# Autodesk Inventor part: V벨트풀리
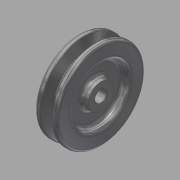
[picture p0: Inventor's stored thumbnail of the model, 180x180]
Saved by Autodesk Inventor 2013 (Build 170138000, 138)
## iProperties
Created: 2015-11
Part Number: V벨트풀리
Material: 강철, 탄소
Document SubType Name: Modeling
Designer: mduedu
Density: 7.87 g/cm^3
Mass: 415.435 g
Surface Area: 174.543 cm^2
Volume: 52.7872 cm^3
Author: mduedu
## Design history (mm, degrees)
sketch "스케치1"
  geometry: L1 (-9.5, 0)-(9.5, 0); L2 (0, 0)-(0, 37.7); L3 (-4.825, 37.7)-(-9.5, 37.7); L4 (-9.5, 37.7)-(-9.5, 0); L5 (0, 28.7)-(-2.074, 28.7); L6 (-2.074, 28.7)-(-4.825, 37.7); L7 (4.825, 37.7)-(9.5, 37.7); L8 (9.5, 37.7)-(9.5, 0); L9 (0, 28.7)-(2.074, 28.7); L10 (2.074, 28.7)-(4.825, 37.7); L11 (-9.5, 35)-(9.5, 35); 3 further points
  constraints: 22 end point, 7 point on line, 4 perpendicular, 3 symmetric about line, 1 coincident, 1 horizontal, 1 horizontal alignment, 1 midpoint, 1 vertical
  dimensions: "d0" = 19 distance of L1.start L1.end; "d2" = 75.4 diameter of L2.end L1 (derived); "d3" = 34 deg angle of L10 L6; "d4" = 6.3 distance between parallel lines of L11 L9; "d5" = 2.7 distance between parallel lines of L7 L11; "d6" = 8 distance of point (4, 35) point (-4, 35); "d7" = 70 diameter of L11 L1
revolve "회전1" sketch "스케치1" stored, may be unused: angle "d8" = 90 deg
sketch "스케치2"
  geometry: C1 r 24 at (0, 0); C2 r 11 at (0, 0); 1 further point
  constraints: 2 centre point, 2 coincident
  dimensions: "d9" = 48 diameter of C1; "d10" = 22 diameter of C2
extrude "돌출1" cut sketch "스케치2" distance "d11" = 6; taper "d12" = 0 deg
fillet "모깎기1" dims "d13" = 3
fillet "모깎기2" dims "d14" = 3
fillet "모깎기3" dims "d15" = 1, "d16" = 0.5, "d17" = 2
hole "구멍1" diameter "d20" = 10; stored, may be unused: countersink angle "d24" = 90 deg, drill point angle "d26" = 118 deg; dims "d18" = 10, "d19" = 10, "d21" = 6, "d22" = 4, "d23" = 2, "d25" = 8
sketch "스케치3"
  geometry: L1 (-1.5, 0)-(1.5, 0); L2 (1.5, 0)-(1.5, 6.4); L3 (1.5, 6.4)-(-1.5, 6.4); L4 (-1.5, 6.4)-(-1.5, 0); 2 further points
  constraints: 8 end point, 2 parallel, 1 coincident, 1 horizontal, 1 midpoint, 1 perpendicular
  dimensions: "d27" = 3 distance of L2.end L3.end; "d29" = 6.4 distance of L3.end L1.start
extrude "돌출2" cut sketch "스케치3" stored distance "d30" = 6; taper "d31" = 0 deg
chamfer "모따기1" distance "d32" = 0.5; stored, may be unused: second distance "d33" = 2, angle "d34" = 45 deg
node "솔리드1"
mirror "대칭1"
